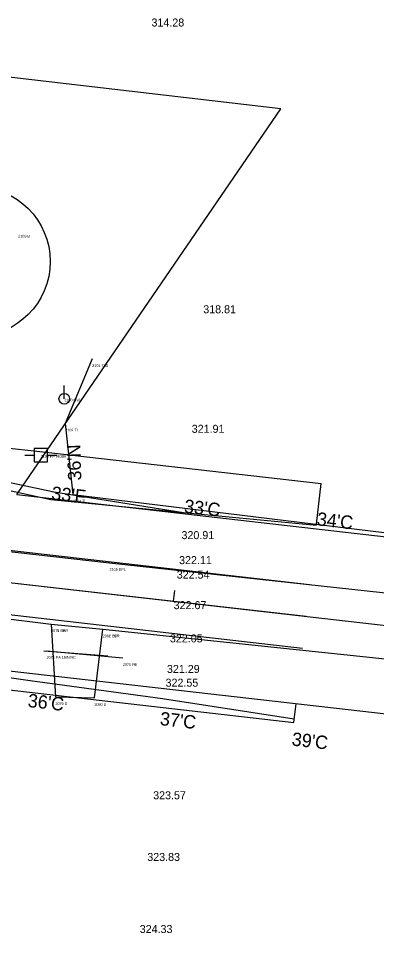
# Model space of a CAD drawing. Extents: x 49683 to 58852, y 49525 to 54803.
# Drawn here: x 57135.4 to 57269.8, y 53907 to 54251 of the extents above; entities that cross this region are included whole.
import ezdxf

# ---------------------------------------------------------------- set-up
doc = ezdxf.new("R2010")
doc.units = 0
for name, color, linetype in [('Level 1', 7, 'Continuous'), ('Level 11', 7, 'Continuous'), ('Level 12', 7, 'Continuous'), ('Level 13', 7, 'Continuous'), ('Level 18', 7, 'Continuous'), ('Level 19', 7, 'Continuous'), ('Level 20', 7, 'Continuous'), ('Level 25', 7, 'Continuous'), ('Level 3', 7, 'Continuous'), ('Level 32', 7, 'Continuous'), ('Level 33', 7, 'Continuous'), ('Level 34', 7, 'Continuous'), ('Level 48', 7, 'Continuous'), ('Level 53', 7, 'Continuous'), ('Level 56', 7, 'Continuous'), ('Level 58', 7, 'Continuous'), ('Level 59', 7, 'Continuous'), ('Level 6', 7, 'Continuous'), ('Level 61', 7, 'Continuous'), ('Level 8', 7, 'Continuous'), ('Level 9', 7, 'Continuous')]:
    doc.layers.add(name, color=color, linetype=linetype)

# ---------------------------------------------------------------- blocks, each defined once
blk = doc.blocks.new('GW')
at = {"layer": 'Level 9'}
blk.add_line((0, 0), (0, 5), dxfattribs=at)
blk.add_circle((0, 0), 2, dxfattribs=at)
blk = doc.blocks.new('PP')
at = {"layer": 'Level 9'}
for p, q in [((2.53, 2.45), (-2.47, 2.45)), ((-2.47, 2.45), (-2.47, -2.55)), ((2.53, -2.55), (2.53, 2.45)), ((-5.91, -0.11), (-2.44, -0.11)), ((-2.47, -2.55), (2.53, -2.55)), ((2.45, -0.11), (6.09, -0.11))]:
    blk.add_line(p, q, dxfattribs=at)

msp = doc.modelspace()

# ---------------------------------------------------------------- linework, layer by layer
at = {"layer": 'Level 1'}
for p, q in [((56981.58, 54056.82), (58783.3, 53851.37)), ((57193.61, 54032.65), (57194.06, 54036.62))]:
    msp.add_line(p, q, dxfattribs=at)
at = {"layer": 'Level 11'}
for p, q in [((57163.12, 54123.38), (57152.99, 54099.2)), ((57152.99, 54099.2), (57155.88, 54072.62)), ((57155.88, 54072.62), (57290.67, 54056.11))]:
    msp.add_line(p, q, dxfattribs=at)
at = {"layer": 'Level 12'}
for p, q in [((57233.86, 54217.04), (57083.33, 54234.58)), ((57134.79, 54072.57), (57233.86, 54217.04))]:
    msp.add_line(p, q, dxfattribs=at)
at = {"layer": 'Level 13'}
for p, q in [((57134.79, 54072.57), (58787.04, 53884.15)), ((57314.41, 53985.66), (56917.82, 54030.88))]:
    msp.add_line(p, q, dxfattribs=at)
at = {"layer": 'Level 18'}
for p, q in [((57099.15, 54084.24), (57148.26, 54073.66)), ((57098.51, 54081.31), (57147.63, 54070.73)), ((57147.93, 54073.72), (57197.4, 54065.84)), ((57147.63, 54070.73), (57197.4, 54065.84)), ((57197.4, 54065.84), (57247.18, 54061.05)), ((57090.37, 54009.92), (57139.9, 54002.97)), ((57139.9, 54002.97), (57189.46, 53996.19)), ((57189.46, 53996.19), (57238.9, 53988.52))]:
    msp.add_line(p, q, dxfattribs=at)
at = {"layer": 'Level 19'}
msp.add_line((56901.29, 54065.98), (57243.29, 54026.98), dxfattribs=at)
at = {"layer": 'Level 20'}
for p, q in [((57030.57, 54063.31), (57244.65, 54038.9)), ((56980.23, 54044.9), (57241.93, 54015.06))]:
    msp.add_line(p, q, dxfattribs=at)
at = {"layer": 'Level 25'}
msp.add_circle((57119.31, 54159.87), 28.04, dxfattribs=at)
at = {"layer": 'Level 3'}
for p, q in [((57082.6, 54056.87), (57169.61, 54047.04)), ((56979.43, 54044.34), (57147.69, 54024.06)), ((57169.61, 54047.04), (57289.1, 54034.02)), ((57147.69, 54024.06), (57167.04, 54022.13)), ((57167.04, 54022.13), (57289.26, 54009.3))]:
    msp.add_line(p, q, dxfattribs=at)
at = {"layer": 'Level 33'}
for p, q in [((57026.81, 54101.99), (57145.67, 54088.44)), ((57145.67, 54088.44), (57248.95, 54076.66)), ((57247.21, 54061.43), (57248.95, 54076.66)), ((56990.37, 54015.56), (57238.75, 53987.24)), ((57238.75, 53987.24), (57239.55, 53994.19))]:
    msp.add_line(p, q, dxfattribs=at)
at = {"layer": 'Level 34'}
msp.add_line((57144.98, 54014.04), (57168.91, 54012.18), dxfattribs=at)
at = {"layer": 'Level 6'}
msp.add_line((57145.99, 54014.05), (57174.6, 54011.38), dxfattribs=at)
at = {"layer": 'Level 8'}
for p, q in [((57147.69, 54024.06), (57149.32, 53996.75)), ((57163.93, 53996.41), (57167.04, 54022.13)), ((57149.32, 53996.75), (57163.93, 53996.41))]:
    msp.add_line(p, q, dxfattribs=at)

# ---------------------------------------------------------------- block references
at = {"layer": 'Level 9'}
for name, p in [('GW', (57152.65, 54108.46)), ('PP', (57143.77, 54087.39))]:
    msp.add_blockref(name, p, dxfattribs=at)

# ---------------------------------------------------------------- texts
at = {"layer": 'Level 32'}
for s, p in [('314.28', (57185.34, 54247.92)), ('318.81', (57204.76, 54140.49)), ('321.91', (57200.43, 54095.7)), ('320.91', (57196.59, 54055.88)), ('322.11', (57195.68, 54046.51)), ('322.54', (57194.82, 54041.1)), ('322.67', (57193.64, 54029.64)), ('322.05', (57192.25, 54017.19)), ('321.29', (57191.14, 54005.74)), ('322.55', (57190.62, 54000.6)), ('323.57', (57185.97, 53958.42)), ('323.83', (57183.76, 53935.31)), ('324.33', (57180.93, 53908.31))]:
    msp.add_text(s, height=3, dxfattribs=at).set_placement(p)
at = {"layer": 'Level 48'}
for s, rotation, p in [("36'N", 92.1896, (57159.09, 54077.91)), ("33'F", 353.4944, (57147.63, 54070.73)), ("33'C", 353.4944, (57197.4, 54065.84)), ("34'C", 353.4944, (57247.18, 54061.05)), ("36'C", 353.4944, (57138.77, 53993.03)), ("37'C", 353.4944, (57188.32, 53986.25)), ("39'C", 353.4944, (57237.77, 53978.58))]:
    msp.add_text(s, height=5, rotation=rotation, dxfattribs=at).set_placement(p)
at = {"layer": 'Level 53'}
for s, p in [('2105 EPL ', (57169.61, 54044.04)), ('2077 EPR ', (57147.69, 54021.06)), ('2082 EPR ', (57167.04, 54019.13))]:
    msp.add_text(s, height=1, dxfattribs=at).set_placement(p)
at = {"layer": 'Level 56'}
for s, p in [('2075 PA 15IN RC ', (57145.99, 54011.05)), ('2076 PB ', (57174.6, 54008.38))]:
    msp.add_text(s, height=1, dxfattribs=at).set_placement(p)
at = {"layer": 'Level 58'}
for s, p in [('2169 B ', (57135.38, 54168.87)), ('2078 DA ', (57147.69, 54021.06)), ('2081 DB ', (57167.04, 54019.13)), ('2079 D ', (57149.32, 53993.75)), ('2080 D ', (57163.93, 53993.41))]:
    msp.add_text(s, height=1, dxfattribs=at).set_placement(p)
at = {"layer": 'Level 59'}
for s, p in [('2100 GW ', (57152.65, 54107.46)), ('2103 PP 96386 ', (57143.77, 54086.39))]:
    msp.add_text(s, height=1, dxfattribs=at).set_placement(p)
at = {"layer": 'Level 61'}
for s, p in [('2101 TLA ', (57163.12, 54120.38)), ('2102 TL ', (57152.99, 54096.2)), ('2104 TL ', (57155.88, 54069.62))]:
    msp.add_text(s, height=1, dxfattribs=at).set_placement(p)

doc.saveas('drawing.dxf')
